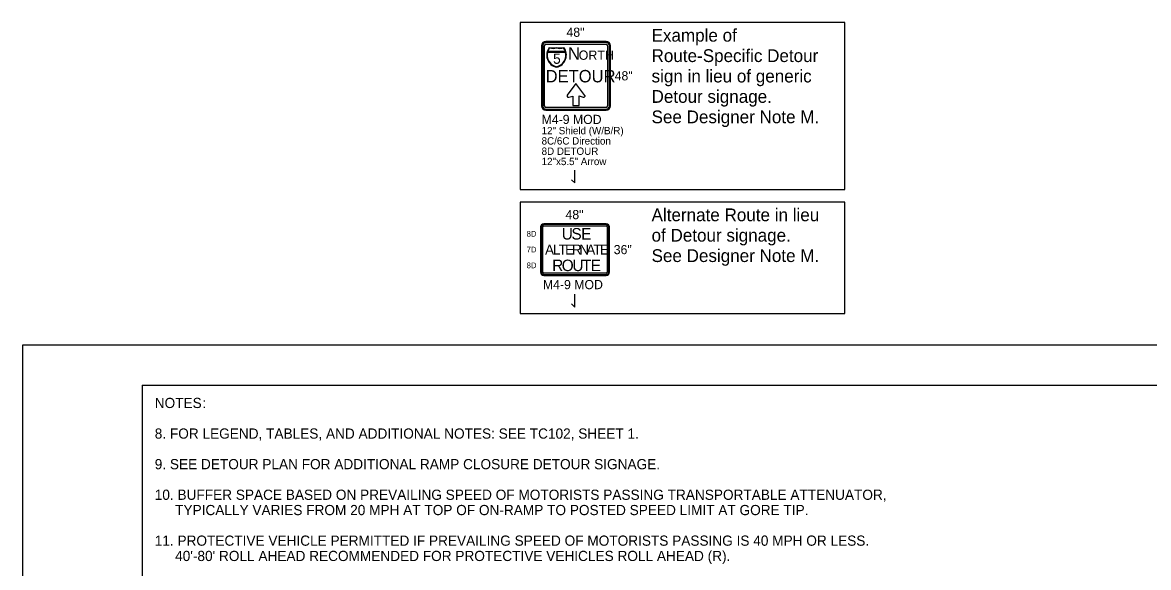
# Model space of a CAD drawing. Extents: x 99999.1 to 100055.7, y 99995 to 100013.2.
# Drawn here: x 100019.06 to 100027.9, y 100008.94 to 100013.22 of the extents above; entities that cross this region are included whole.
import ezdxf

# ---------------------------------------------------------------- set-up
doc = ezdxf.new("R2010")
doc.units = 0
for name, color, linetype in [('SH_GI_GeneralNotesBodyText', 7, 'Continuous'), ('SH_GI_PlotLimits', 7, 'Continuous'), ('SH_GI_SheetBorder', 7, 'Continuous'), ('TR_SN_ConstructionSigns', 7, 'Continuous'), ('TR_WZ_WorkZoneDetails', 7, 'Continuous')]:
    doc.layers.add(name, color=color, linetype=linetype)

msp = doc.modelspace()

# ---------------------------------------------------------------- linework, layer by layer
at = {"layer": 'SH_GI_PlotLimits'}
msp.add_lwpolyline([(100019.0625, 99999.6875), (100036.0625, 99999.6875), (100036.0625, 100010.6875), (100019.0625, 100010.6875)], close=True, dxfattribs=at)
at = {"layer": 'SH_GI_SheetBorder'}
for q in [(100020, 100000), (100035.75, 100010.375)]:
    msp.add_line((100020, 100010.375), q, dxfattribs=at)
at = {"layer": 'TR_SN_ConstructionSigns'}
for p, q in [((100023.1354, 100013.0373), (100023.1354, 100012.5648)), ((100023.1438, 100013.0373), (100023.1438, 100012.5648)), ((100023.1579, 100012.5648), (100023.1579, 100013.0373)), ((100023.6416, 100013.0711), (100023.1691, 100013.0711)), ((100023.6416, 100013.0626), (100023.1691, 100013.0626)), ((100023.1691, 100013.0486), (100023.6416, 100013.0486)), ((100023.6529, 100013.0373), (100023.6529, 100012.5648)), ((100023.6669, 100012.5648), (100023.6669, 100013.0373)), ((100023.6754, 100012.5648), (100023.6754, 100013.0373)), ((100023.3228, 100012.9875), (100023.1823, 100012.9875)), ((100023.1823, 100012.9875), (100023.3228, 100012.9875)), ((100023.1834, 100012.9912), (100023.3217, 100012.9912)), ((100023.3217, 100012.9912), (100023.1834, 100012.9912)), ((100023.6416, 100012.5536), (100023.1691, 100012.5536)), ((100023.1691, 100012.5395), (100023.6416, 100012.5395)), ((100023.1691, 100012.5311), (100023.6416, 100012.5311)), ((100023.6424, 100011.6405), (100023.153, 100011.6405)), ((100023.6424, 100011.6335), (100023.153, 100011.6335)), ((100023.153, 100011.6236), (100023.6424, 100011.6236)), ((100023.1277, 100011.6152), (100023.1277, 100011.2608)), ((100023.1347, 100011.6152), (100023.1347, 100011.2608)), ((100023.1446, 100011.2608), (100023.1446, 100011.6152)), ((100023.6508, 100011.6152), (100023.6508, 100011.2608)), ((100023.6607, 100011.2608), (100023.6607, 100011.6152)), ((100023.6677, 100011.2608), (100023.6677, 100011.6152)), ((100023.6424, 100011.2524), (100023.153, 100011.2524)), ((100023.153, 100011.2425), (100023.6424, 100011.2425)), ((100023.153, 100011.2355), (100023.6424, 100011.2355))]:
    msp.add_line(p, q, dxfattribs=at)
msp.add_lwpolyline([(100023.3367, 100012.6494), (100023.3356, 100012.6478), (100023.335, 100012.6461), (100023.3347, 100012.6441), (100023.3348, 100012.6424), (100023.335, 100012.6412), (100023.3356, 100012.6398), (100023.3373, 100012.6375), (100023.3386, 100012.6364), (100023.34, 100012.6355), (100023.3417, 100012.6348), (100023.3432, 100012.6345), (100023.3447, 100012.6343), (100023.3465, 100012.6343), (100023.3478, 100012.6346), (100023.3795, 100012.6424), (100023.3795, 100012.5671), (100023.4307, 100012.5671), (100023.4307, 100012.6429), (100023.4617, 100012.6337), (100023.4647, 100012.6331), (100023.4681, 100012.6334), (100023.4703, 100012.6342), (100023.4733, 100012.6362), (100023.4752, 100012.6389), (100023.476, 100012.6414), (100023.4761, 100012.6436), (100023.4754, 100012.6463), (100023.4746, 100012.6477), (100023.4051, 100012.7405), (100023.3367, 100012.6494)], dxfattribs=at)
for centre, radius, start, end in [((100023.1691, 100013.0373), 0.0337, 90, 180), ((100023.1691, 100013.0373), 0.0253, 90, 180), ((100023.1691, 100013.0373), 0.0113, 90, 180), ((100023.6416, 100013.0373), 0.0338, 360, 90), ((100023.6416, 100013.0373), 0.0253, 360, 90), ((100023.6416, 100013.0373), 0.0113, 360, 90), ((100023.2725, 100012.9642), 0.0973, 142.16169, 258.18105), ((100023.2715, 100012.9633), 0.0925, 164.85517, 258.18105), ((100023.2715, 100012.9633), 0.0925, 164.85517, 258.18105), ((100023.2715, 100012.9633), 0.0925, 142.16169, 162.48397), ((100023.2715, 100012.9633), 0.0925, 142.16169, 162.48397), ((100023.2245, 100013.1212), 0.1014, 253.48525, 286.04538), ((100023.2259, 100013.1124), 0.0964, 253.48525, 286.04538), ((100023.2259, 100013.1124), 0.0964, 253.48525, 286.04538), ((100023.2806, 100013.1212), 0.1014, 253.95462, 286.51475), ((100023.2792, 100013.1124), 0.0964, 253.95462, 286.51475), ((100023.2792, 100013.1124), 0.0964, 253.95462, 286.51475), ((100023.2325, 100012.9642), 0.0974, 281.90384, 37.84925), ((100023.2335, 100012.9633), 0.0925, 281.90384, 15.1558), ((100023.2335, 100012.9633), 0.0925, 281.90384, 15.1558), ((100023.2335, 100012.9633), 0.0925, 17.52691, 37.84925), ((100023.2335, 100012.9633), 0.0925, 17.52691, 37.84925), ((100023.1691, 100012.5648), 0.0338, 180, 270), ((100023.1691, 100012.5648), 0.0253, 180, 270), ((100023.1691, 100012.5648), 0.0113, 180, 270), ((100023.6416, 100012.5648), 0.0337, 270, 360), ((100023.6416, 100012.5648), 0.0253, 270, 0), ((100023.6416, 100012.5648), 0.0113, 270, 0), ((100023.153, 100011.6152), 0.0253, 90, 180), ((100023.153, 100011.6152), 0.0183, 90, 180), ((100023.153, 100011.6152), 0.00844, 90, 180), ((100023.6424, 100011.6152), 0.0253, 360, 90), ((100023.6424, 100011.6152), 0.0183, 360, 90), ((100023.6424, 100011.6152), 0.00844, 360, 90), ((100023.153, 100011.2608), 0.0253, 180, 270), ((100023.153, 100011.2608), 0.0183, 180, 270), ((100023.153, 100011.2608), 0.00844, 180, 270), ((100023.6424, 100011.2608), 0.0253, 270, 360), ((100023.6424, 100011.2608), 0.0183, 270, 0), ((100023.6424, 100011.2608), 0.00844, 270, 0)]:
    msp.add_arc(centre, radius, start, end, dxfattribs=at)
at = {"layer": 'TR_WZ_WorkZoneDetails'}
for p, q in [((100023.3963, 100011.9605), (100023.3963, 100012.0605)), ((100023.3713, 100011.9855), (100023.3963, 100011.9605)), ((100023.3963, 100010.9875), (100023.3963, 100011.0875)), ((100023.3713, 100011.0125), (100023.3963, 100010.9875))]:
    msp.add_line(p, q, dxfattribs=at)
for points in [[(100022.9666, 100011.9105), (100025.5143, 100011.9105), (100025.5143, 100013.2191), (100022.9666, 100013.2191)], [(100022.9666, 100010.9375), (100025.5143, 100010.9375), (100025.5143, 100011.8105), (100022.9666, 100011.8105)]]:
    msp.add_lwpolyline(points, close=True, dxfattribs=at)

# ---------------------------------------------------------------- texts
at = {"layer": 'SH_GI_GeneralNotesBodyText'}
for s, p in [('NOTES', (100020.1, 100010.195)), (':', (100020.4743, 100010.195)), ('8. FOR LEGEND, TABLES, AND ADDITIONAL NOTES: SEE TC102, SHEET 1.', (100020.1, 100009.955)), ('9. SEE DETOUR PLAN FOR ADDITIONAL RAMP CLOSURE DETOUR SIGNAGE.', (100020.1, 100009.715)), ('10. BUFFER SPACE BASED ON PREVAILING SPEED OF MOTORISTS PASSING TRANSPORTABLE ATTENUATOR, ', (100020.1, 100009.475)), ('TYPICALLY VARIES FROM 20 MPH AT TOP OF ON-RAMP TO POSTED SPEED LIMIT AT GORE TIP.', (100020.26, 100009.355)), ('11. PROTECTIVE VEHICLE PERMITTED IF PREVAILING SPEED OF MOTORISTS PASSING IS 40 MPH OR LESS.  ', (100020.1, 100009.115)), ("40'-80' ROLL AHEAD RECOMMENDED FOR PROTECTIVE VEHICLES ROLL AHEAD (R).", (100020.26, 100008.995))]:
    msp.add_text(s, height=0.08, rotation=360, dxfattribs=at).set_placement(p)
at = {"layer": 'TR_SN_ConstructionSigns'}
for s, height, p in [('48"', 0.072, (100023.3306, 100013.1071)), ('5', 0.081, (100023.2253, 100012.8951)), ('N', 0.0972, (100023.3432, 100012.9267)), ('ORTH', 0.0729, (100023.4264, 100012.9267)), ('DETOUR', 0.0972, (100023.1668, 100012.7497)), ('48"', 0.072, (100023.7086, 100012.7651)), ('M4-9 MOD', 0.072, (100023.1354, 100012.4231)), ('12" Shield (W/B/R)', 0.0576, (100023.1354, 100012.3424)), ('8C/6C Direction', 0.0576, (100023.1354, 100012.2618)), ('8D DETOUR', 0.0576, (100023.1354, 100012.1811)), ('12"x5.5" Arrow', 0.0576, (100023.1354, 100012.1005)), ('48"', 0.072, (100023.323, 100011.6765)), ('36"', 0.072, (100023.7015, 100011.402)), ('M4-9 MOD', 0.072, (100023.1457, 100011.1275))]:
    msp.add_text(s, height=height, rotation=360, dxfattribs=at).set_placement(p)
for s, height, p in [('8D', 0.045, (100023.018, 100011.5392)), ('U', 0.09, (100023.2933, 100011.5167)), ('S', 0.09, (100023.3698, 100011.5167)), ('E', 0.09, (100023.4463, 100011.5167)), ('7D', 0.045, (100023.018, 100011.4155)), ('A', 0.0787, (100023.1626, 100011.3986)), ('L', 0.0787, (100023.2241, 100011.3986)), ('T', 0.0787, (100023.269, 100011.3986)), ('E', 0.0787, (100023.3201, 100011.3986)), ('R', 0.0787, (100023.3737, 100011.3986)), ('N', 0.0787, (100023.4312, 100011.3986)), ('A', 0.0787, (100023.4863, 100011.3986)), ('T', 0.0787, (100023.5414, 100011.3986)), ('E', 0.0787, (100023.5926, 100011.3986)), ('R', 0.09, (100023.2186, 100011.2692)), ('O', 0.09, (100023.2933, 100011.2692)), ('U', 0.09, (100023.377, 100011.2692)), ('T', 0.09, (100023.4517, 100011.2692)), ('E', 0.09, (100023.521, 100011.2692)), ('8D', 0.045, (100023.018, 100011.2917))]:
    msp.add_text(s, height=height, dxfattribs=at).set_placement(p)
at = {"layer": 'TR_WZ_WorkZoneDetails'}
for s, p in [('Example of ', (100023.9983, 100013.0691)), ('Route-Specific Detour ', (100023.9983, 100012.9091)), ('sign in lieu of generic ', (100023.9983, 100012.7491)), ('Detour signage.', (100023.9983, 100012.5891)), ('See Designer Note M.', (100023.9983, 100012.4291)), ('Alternate Route in lieu ', (100023.9983, 100011.6605)), ('of Detour signage.', (100023.9983, 100011.5005)), ('See Designer Note M.', (100023.9983, 100011.3405))]:
    msp.add_text(s, height=0.1, dxfattribs=at).set_placement(p)

doc.saveas('drawing.dxf')
